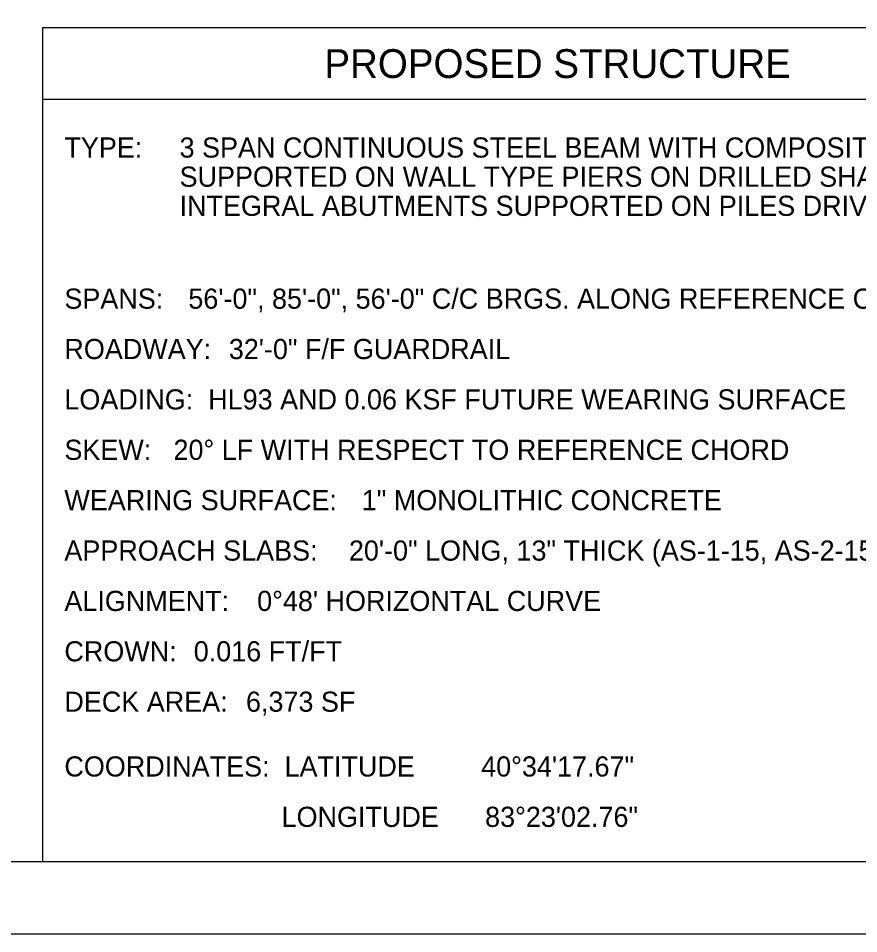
# Model space of a CAD drawing. Extents: x 0 to 34, y 0 to 22.
# Drawn here: x 24.58 to 30.42, y 0 to 6.36 of the extents above; entities that cross this region are included whole.
import ezdxf

# ---------------------------------------------------------------- set-up
doc = ezdxf.new("R2010")
doc.units = 0
for name, color, linetype in [('DT_X_Contour_Major', 7, 'Continuous'), ('DT_X_Spot_Elev', 7, 'Continuous'), ('DT_X_Triangles', 7, 'Continuous')]:
    doc.layers.add(name, color=color, linetype=linetype)

msp = doc.modelspace()

# ---------------------------------------------------------------- linework, layer by layer
at = {"layer": 'DT_X_Contour_Major'}
msp.add_lwpolyline([(0, 0), (34, 0), (34, 22), (0, 22)], close=True, dxfattribs=at)
at = {"layer": 'DT_X_Spot_Elev'}
msp.add_lwpolyline([(1.5, 21.5), (33.5, 21.5), (33.5, 0.5), (1.5, 0.5)], close=True, dxfattribs=at)
at = {"layer": 'DT_X_Triangles'}
msp.add_line((31.9999, 5.795), (24.7499, 5.795), dxfattribs=at)
msp.add_lwpolyline([(24.7499, 6.295), (31.9999, 6.295), (31.9999, 0.5), (24.7499, 0.5)], close=True, dxfattribs=at)

# ---------------------------------------------------------------- texts
for s, height, p in [('PROPOSED STRUCTURE', 0.2, (26.7055, 5.945)), ('3 SPAN CONTINUOUS STEEL BEAM WITH COMPOSITE DECK', 0.14, (25.6999, 5.3919)), ('TYPE:', 0.14, (24.8999, 5.3919)), ('TYPE:', 0.14, (24.8999, 5.3919)), ('SUPPORTED ON WALL TYPE PIERS ON DRILLED SHAFTS, AND', 0.14, (25.6999, 5.1894)), ('INTEGRAL ABUTMENTS SUPPORTED ON PILES DRIVEN TO ROCK.', 0.14, (25.6999, 4.9869)), ('SPANS:', 0.14, (24.8999, 4.3419)), ('SPANS:', 0.14, (24.8999, 4.3419)), ('56\'-0", 85\'-0", 56\'-0" C/C BRGS. ALONG REFERENCE CHORD', 0.14, (25.7608, 4.3419)), ('ROADWAY:', 0.14, (24.8999, 3.9919)), ('ROADWAY:', 0.14, (24.8999, 3.9919)), ('32\'-0" F/F GUARDRAIL', 0.14, (26.0419, 3.9919)), ('LOADING:  HL93 AND 0.06 KSF FUTURE WEARING SURFACE', 0.14, (24.8999, 3.6419)), ('SKEW:', 0.14, (24.8999, 3.2919)), ('SKEW:', 0.14, (24.8999, 3.2919)), ('20° LF WITH RESPECT TO REFERENCE CHORD', 0.14, (25.6577, 3.2919)), ('WEARING SURFACE:', 0.14, (24.8999, 2.9419)), ('WEARING SURFACE:', 0.14, (24.8999, 2.9419)), ('1" MONOLITHIC CONCRETE', 0.14, (26.9653, 2.9419)), ('20\'-0" LONG, 13" THICK (AS-1-15, AS-2-15 TYPE C)', 0.14, (26.876, 2.5919)), ('APPROACH SLABS:', 0.14, (24.8999, 2.5919)), ('APPROACH SLABS:', 0.14, (24.8999, 2.5919)), ('ALIGNMENT:', 0.14, (24.8999, 2.2419)), ('ALIGNMENT:', 0.14, (24.8999, 2.2419)), ("0°48' HORIZONTAL CURVE", 0.14, (26.2387, 2.2419)), ('0.016 FT/FT', 0.14, (25.7983, 1.8919)), ('CROWN:', 0.14, (24.8999, 1.8919)), ('CROWN:', 0.14, (24.8999, 1.8919)), ('DECK AREA:', 0.14, (24.8999, 1.5419)), ('DECK AREA:', 0.14, (24.8999, 1.5419)), ('6,373 SF', 0.14, (26.1611, 1.5419)), ('COORDINATES:  LATITUDE', 0.14, (24.8999, 1.0919)), ('COORDINATES:  LATITUDE', 0.14, (24.8999, 1.0919)), ('40°34\'17.67"', 0.14, (27.7945, 1.0919)), ('                             LONGITUDE', 0.14, (24.8999, 0.7419)), ('                             LONGITUDE', 0.14, (24.8999, 0.7419)), ('83°23\'02.76"', 0.14, (27.8218, 0.7419))]:
    msp.add_text(s, height=height, dxfattribs=at).set_placement(p)

doc.saveas('drawing.dxf')
